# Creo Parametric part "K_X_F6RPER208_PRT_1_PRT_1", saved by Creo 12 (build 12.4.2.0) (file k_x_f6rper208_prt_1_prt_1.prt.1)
Units: Custom; MM, KILOGRAM, SECS

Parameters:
  PTC_WM_ITERATION = "0"
  PTC_WM_VERSION = "-.0"
  PTC_WM_LIFECYCLE_STATE = "In Work"
  PTC_WM_LIFECYCLE = "MO_CADDocument"
  PTC_WM_CREATED_BY = "Maximilian Roepper (Z0017RMS: MO)"
  PTC_WM_CREATED_ON = "18-Sep-26 11:36:42 AM"
  PTC_WM_MODIFIED_BY = "Maximilian Roepper (Z0017RMS: MO)"
  PTC_WM_MODIFIED_ON = "18-Sep-26 11:36:46 AM"
  PDMLINKNUMBER = "PDM000071454926"
  PTC_WM_NAME = "k_x_f6rper208_prt_1_prt_1.prt"
  PTC_WM_NUMBER = "PDM000071454926"

Other parameters: WEIGHT, WEIGHT_FACTOR, WEIGHT_ADD, _MASS_TEMP, _DIFF_TEMP, MC_ERRORS, SUPPLIER

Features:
  1. coordinate system
  2. datum plane "PRT_YZ"
  3. datum plane "PRT_XY"
  4. datum plane "PRT_XZ"
  5. coordinate system
  6. datum axis
  7. datum axis
  8. datum axis
  9. coordinate system
  10. imported feature
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
Other named items: PRT, SIEMENS_MO, DRW_VIEW_ORG, PRT_X, PRT_Y, PRT_Z, CS0, ROUGH_GROB

Layers: 00_STD_CSYS-KSYS, 01_STD_PLANES-EBENEN, 02_STD_AXES-ACHSEN, 03_STD_CSYS-KSYS, 24_IMPORT_FEAT-IMPORT_KE

Surfaces: 33 tabulated cylinder, 2 plane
